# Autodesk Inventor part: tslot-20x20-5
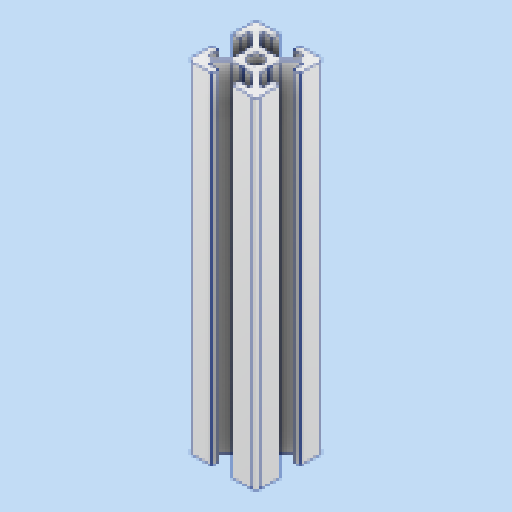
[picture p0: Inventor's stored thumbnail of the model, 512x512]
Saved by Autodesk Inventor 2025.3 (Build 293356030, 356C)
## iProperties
Created: 2025-03
Part Number: tslot-20x20-5
Material: Alluminio 6061
Document SubType Name: Modeling
Designer: Ryzen5700u
Density: 2.7 g/cm^3
Appearance: Alluminio - Piatto
Author: Ryzen5700u
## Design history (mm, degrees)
feature "Base1"
sketch "Schizzo1"
  geometry: L1 (3.761, -16)-(4.7, -16) reference; L2 (3.761, -16)-(0.7, -12.939) reference; L3 (0.7, -12.939)-(0.7, -10.52) reference; L4 (0.4, -10)-(0.7, -10.52) reference; L5 (0.4, -10)-(0.7, -9.48) reference; L6 (0.7, -7.061)-(0.7, -9.48) reference; L7 (3.761, -4)-(0.7, -7.061) reference; L8 (3.761, -4)-(4.7, -4) reference; L9 (4.7, -4)-(4.7, -7) reference; L10 (4.7, -7)-(6.4, -7) reference; L11 (6.7, -6.7)-(6.7, -1) reference; L12 (5.7, 0)-(0, 0) reference; L13 (-0.3, -2)-(-0.3, -0.3) reference; L14 (2.7, -2)-(-0.3, -2) reference; L15 (2.7, -2.939)-(2.7, -2) reference; L16 (2.7, -2.939)-(-0.361, -6) reference; L17 (-0.361, -6)-(-2.78, -6) reference; L18 (-3.3, -6.3)-(-2.78, -6) reference; L19 (-3.3, -6.3)-(-3.82, -6) reference; L20 (-6.239, -6)-(-3.82, -6) reference; L21 (-9.3, -2.939)-(-6.239, -6) reference; L22 (-9.3, -2.939)-(-9.3, -2) reference; L23 (-9.3, -2)-(-6.3, -2) reference; L24 (-6.3, -2)-(-6.3, -0.3) reference; L25 (-12.3, 0)-(-6.6, 0) reference; L26 (-13.3, -6.7)-(-13.3, -1) reference; L27 (-11.3, -7)-(-13, -7) reference; L28 (-11.3, -4)-(-11.3, -7) reference; L29 (-10.361, -4)-(-11.3, -4) reference; L30 (-10.361, -4)-(-7.3, -7.061) reference; L31 (-7.3, -7.061)-(-7.3, -9.48) reference; L32 (-7, -10)-(-7.3, -9.48) reference; L33 (-7, -10)-(-7.3, -10.52) reference; L34 (-7.3, -12.939)-(-7.3, -10.52) reference; L35 (-10.361, -16)-(-7.3, -12.939) reference; L36 (-10.361, -16)-(-11.3, -16) reference; L37 (-11.3, -16)-(-11.3, -13) reference; L38 (-11.3, -13)-(-13, -13) reference; L39 (-13.3, -13.3)-(-13.3, -19) reference; L40 (-12.3, -20)-(-6.6, -20) reference; L41 (-6.3, -18)-(-6.3, -19.7) reference; L42 (-9.3, -18)-(-6.3, -18) reference; L43 (-9.3, -17.061)-(-9.3, -18) reference; L44 (-9.3, -17.061)-(-6.239, -14) reference; L45 (-6.239, -14)-(-3.82, -14) reference; L46 (-3.3, -13.7)-(-3.82, -14) reference; L47 (-3.3, -13.7)-(-2.78, -14) reference; L48 (-0.361, -14)-(-2.78, -14) reference; L49 (2.7, -17.061)-(-0.361, -14) reference; L50 (2.7, -17.061)-(2.7, -18) reference; L51 (2.7, -18)-(-0.3, -18) reference; L52 (-0.3, -18)-(-0.3, -19.7) reference; L53 (5.7, -20)-(0, -20) reference; L54 (6.7, -13.3)-(6.7, -19) reference; L55 (4.7, -13)-(6.4, -13) reference; L56 (4.7, -16)-(4.7, -13) reference; C1 r 2.1 at (-3.3, -10) reference; A1 r 0.3 centre (6.4, -6.7) between (6.4, -7) and (6.7, -6.7) reference; A2 r 1 centre (5.7, -1) between (6.7, -1) and (5.7, 0) reference; A3 r 0.3 centre (0, -0.3) between (0, 0) and (-0.3, -0.3) reference; A4 r 0.3 centre (-6.6, -0.3) between (-6.3, -0.3) and (-6.6, 0) reference; A5 r 1 centre (-12.3, -1) between (-12.3, 0) and (-13.3, -1) reference; A6 r 0.3 centre (-13, -6.7) between (-13.3, -6.7) and (-13, -7) reference; A7 r 0.3 centre (-13, -13.3) between (-13, -13) and (-13.3, -13.3) reference; A8 r 1 centre (-12.3, -19) between (-13.3, -19) and (-12.3, -20) reference; A9 r 0.3 centre (-6.6, -19.7) between (-6.6, -20) and (-6.3, -19.7) reference; A10 r 0.3 centre (0, -19.7) between (-0.3, -19.7) and (0, -20) reference; A11 r 1 centre (5.7, -19) between (5.7, -20) and (6.7, -19) reference; A12 r 0.3 centre (6.4, -13.3) between (6.7, -13.3) and (6.4, -13) reference; 1 further point
extrude "Estrusione1" join sketch "Schizzo1" distance "d0" = 90; taper "d1" = 0 deg
node "Solido1"
node "Linea chiusa proiettata1"
